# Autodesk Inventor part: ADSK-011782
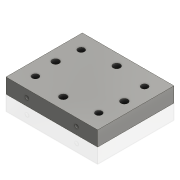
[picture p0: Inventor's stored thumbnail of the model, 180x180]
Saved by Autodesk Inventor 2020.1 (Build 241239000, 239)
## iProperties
Created: 1999-12
Part Number: ADSK-011782
Material: Aluminum
Document SubType Name: Modeling
Designer: tgregory
Density: 2.71 g/cm^3
Appearance: Steel
Mass: 609.097 g
Surface Area: 363.103 cm^2
Volume: 224.759 cm^3
Control State: 0
Checked Out: False
Master: False
Shininess: 0.0
Length Units: 11269
Angle Units: 11279
Time Units: 11290
Mass Units: 11283
Length Display Precision: 3
Angle Display Precision: 2
Compacted: True
Dimensions: 120x19,5x100 mm
Mass: 0,609 kg
Density: 0.0
Volumn: 0.0
Area: 0.0
PropertySet Name: Model Information
Author: tgregory
Revision Number: -
Title: ADSK-011782
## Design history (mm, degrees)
node "Extrusion1" dims "d2" = 100, "d3" = 0
node "Hole1" dims "d8" = 4.917, "d9" = 4, "d10" = 2, "d11" = 60 deg, "d12" = 8, "d13" = 118 deg
node "Hole2" dims "d22" = 8.376, "d23" = 4, "d24" = 2, "d25" = 60 deg, "d26" = 27.3, "d27" = 118 deg, "d49" = 20
node "Hole3" dims "d36" = 8.376, "d37" = 4, "d38" = 2, "d39" = 60 deg, "d40" = 27.3, "d41" = 118 deg, "d50" = 20
node "Hole4" dims "d42" = 4.917, "d43" = 4, "d44" = 2, "d45" = 60 deg, "d46" = 8, "d47" = 118 deg
workplane "Work Plane1"
node "Solide1"
node "Corps solides"
node "Corps surfaciques"
sketch "Sketch1"
  geometry: L1 (0, 0)-(120, 0); L2 (120, 0)-(120, 19.5); L3 (120, 19.5)-(0, 19.5) reference; L4 (0, 19.5)-(0, 0) reference
  constraints: 8 end point, 2 horizontal, 2 parallel, 1 perpendicular, 1 vertical
  dimensions: "d0" = 120 distance between parallel lines of L2 L4; "d1" = 19.5 distance between parallel lines of L3 L1
sketch "Sketch2"
  geometry: L1 (120, 0)-(120, 19.5) reference; L2 (120, 19.5)-(0, 19.5) reference; L3 (0, 19.5)-(0, 0) reference; 2 further points
  dimensions: "d4" = 9.75 distance from line of point (27.5, 9.75) L2; "d5" = 9.75 distance from line of point (92.5, 9.75) L2 (= d4); "d6" = 27.5 distance from line of point (27.5, 9.75) L3; "d7" = 27.5 distance from line of point (92.5, 9.75) L1 (= d6)
sketch "Sketch3"
  geometry: L1 (120, 100)-(0, 100) reference; L2 (0, 0)-(0, 100) reference; L3 (120, 0)-(0, 0) reference; L4 (120, 0)-(120, 100) reference; 4 further points
  dimensions: "d14" = 20 distance from line of point (101.5, 20) L3; "d15" = 20 distance from line of point (101.5, 80) L1 (= d14); "d16" = 18.5 distance from line of point (101.5, 80) L4 (= d21); "d17" = 18.5 distance from line of point (18.5, 80) L2 (= d16); "d18" = 20 distance from line of point (18.5, 80) L1 (= d15); "d19" = 18.5 distance from line of point (18.5, 20) L2 (= d21); "d20" = 20 distance from line of point (18.5, 20) L3 (= d18); "d21" = 18.5 distance from line of point (101.5, 20) L4
sketch "Sketch4"
  geometry: L1 (120, 100)-(0, 100) reference; L2 (0, 0)-(0, 100) reference; L3 (120, 0)-(0, 0) reference; L4 (120, 0)-(120, 100) reference; 4 further points
  dimensions: "d28" = 60 distance from line of point (60, 85) L2; "d29" = 15 distance from line of point (60, 85) L1 (= d31); "d30" = 50 distance from line of point (15, 50) L3; "d31" = 15 distance from line of point (15, 50) L2 (= d35); "d32" = 15 distance from line of point (60, 15) L3 (= d29); "d33" = 60 distance from line of point (60, 15) L4; "d34" = 50 distance from line of L1 point (105, 50); "d35" = 15 distance from line of point (105, 50) L4
sketch "Sketch5"
  geometry: C1 r 2.458 at (-92.5, 9.75) reference; C2 r 2.458 at (-27.5, 9.75) reference; 2 further points
  constraints: 2 coincident
